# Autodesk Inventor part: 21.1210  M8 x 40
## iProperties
Created: 2006-02
Part Number: 21.1210  M8 x 40
Material: Steel, Mild
Description: Cylinder Head Cap Screw
Document SubType Name: Modeling
Standard: DIN 7984
Designer: Andy Moles
Standards Organization: DIN
Language: en-US
Size Designation: M8 x 40
Categories: <MemberInstance><Categories><Category DisplayName="Fasteners" InternalName="e4da775c-781d-43d5-af7c-5136215cf5a6" Mnemonic="FSTN"><Category DisplayName="Bolts"
Density: 7.86 g/cm^3
Mass: 20.1648 g
Surface Area: 15.2032 cm^2
Volume: 2.56549 cm^3
Author: Andy Moles
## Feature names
1. Body [Revolution]
2. Slot [Extrusion]
3. Fillet1
4. Chamfer1
